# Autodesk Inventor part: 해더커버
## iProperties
Company: 한국ATC센터
Created: 2014-01
Part Number: 해더커버
Document SubType Name: Modeling
Designer: KYOUNG IL JANG
Density: 1 g/cm^3
Material: 기본값
Mass: 46.0999 g
Surface Area: 123.575 cm^2
Volume: 46.0999 cm^3
Vendor: CBT Solutions
Author: KYOUNG IL JANG
